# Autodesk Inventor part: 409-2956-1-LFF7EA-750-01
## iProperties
Created: 2010-06
Part Number: 409-2956-1-LFF7EA-750-01
Material: Sch40 CS PIPE SEAMLESS
Description: PIPE
Document SubType Name: Modeling
Designer: S. Boerckel
Engineer: Steve Boerckel
Mass: 11030 g
Surface Area: 7198.1 cm^2
Volume: 1405.09 cm^3
Density: 7.85 g/cm^3
Cost Center: 4"
SMR: =<COST CENTER> - <Material>
Length: 79.797 in
Title: 2"
Author: S. Boerckel
Revision Number: B
Subject: DEMIN WATER FORWARDING PUMP SKID-7EA
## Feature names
1. Extrusion1
